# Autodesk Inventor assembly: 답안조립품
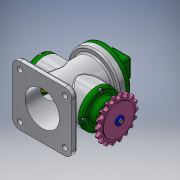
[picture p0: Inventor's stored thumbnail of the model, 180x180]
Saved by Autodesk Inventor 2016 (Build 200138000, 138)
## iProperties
Created: 2021-03
Part Number: 답안조립품
Material: 일반
Document SubType Name: Assembly
Designer: Administrator
Author: Administrator
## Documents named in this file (19)
- C:\Users\Administrator\Desktop\710306V1015\답안조립품.iam
- C:\Users\Administrator\Desktop\710306V1015\본체.ipt
- C:\Users\Administrator\Desktop\710306V1015\E-링.ipt
- C:\Users\Administrator\Desktop\710306V1015\덮개.ipt
- C:\Users\Administrator\Desktop\710306V1015\뒤커버.ipt
- C:\Users\Administrator\Desktop\710306V1015\링크.ipt
- C:\Users\Administrator\Desktop\710306V1015\멈춤나사 M3.ipt
- C:\Users\Administrator\Desktop\710306V1015\베어링 17 x 40 x 12.ipt
- C:\Users\Administrator\Desktop\710306V1015\볼트 M4 x 8.ipt
- C:\Users\Administrator\Desktop\710306V1015\볼트 M4 x 10.ipt
- C:\Users\Administrator\Desktop\710306V1015\스프로킷.ipt
- C:\Users\Administrator\Desktop\710306V1015\슬라이더.ipt
- C:\Users\Administrator\Desktop\710306V1015\앞커버.ipt
- C:\Users\Administrator\Desktop\710306V1015\오일 실 17 30 8.ipt
- C:\Users\Administrator\Desktop\710306V1015\와셔 4x16.ipt
- C:\Users\Administrator\Desktop\710306V1015\클레비스 핀 6 x 22.ipt
- 클레비스 핀 6 x 22.ipt
- C:\Users\Administrator\Desktop\710306V1015\키 4 x 4 x 12.ipt
- C:\Users\Administrator\Desktop\710306V1015\편심축.ipt
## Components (1 placed, 1 different names)
1. E-링:1
